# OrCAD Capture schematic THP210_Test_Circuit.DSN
size A; title: THP210 Ultra-Low Offset, High-Voltage, Low-Noise, Precision,; rev: 1.1; note: Datasheet: SBOS932C   EVM: SBOU234A
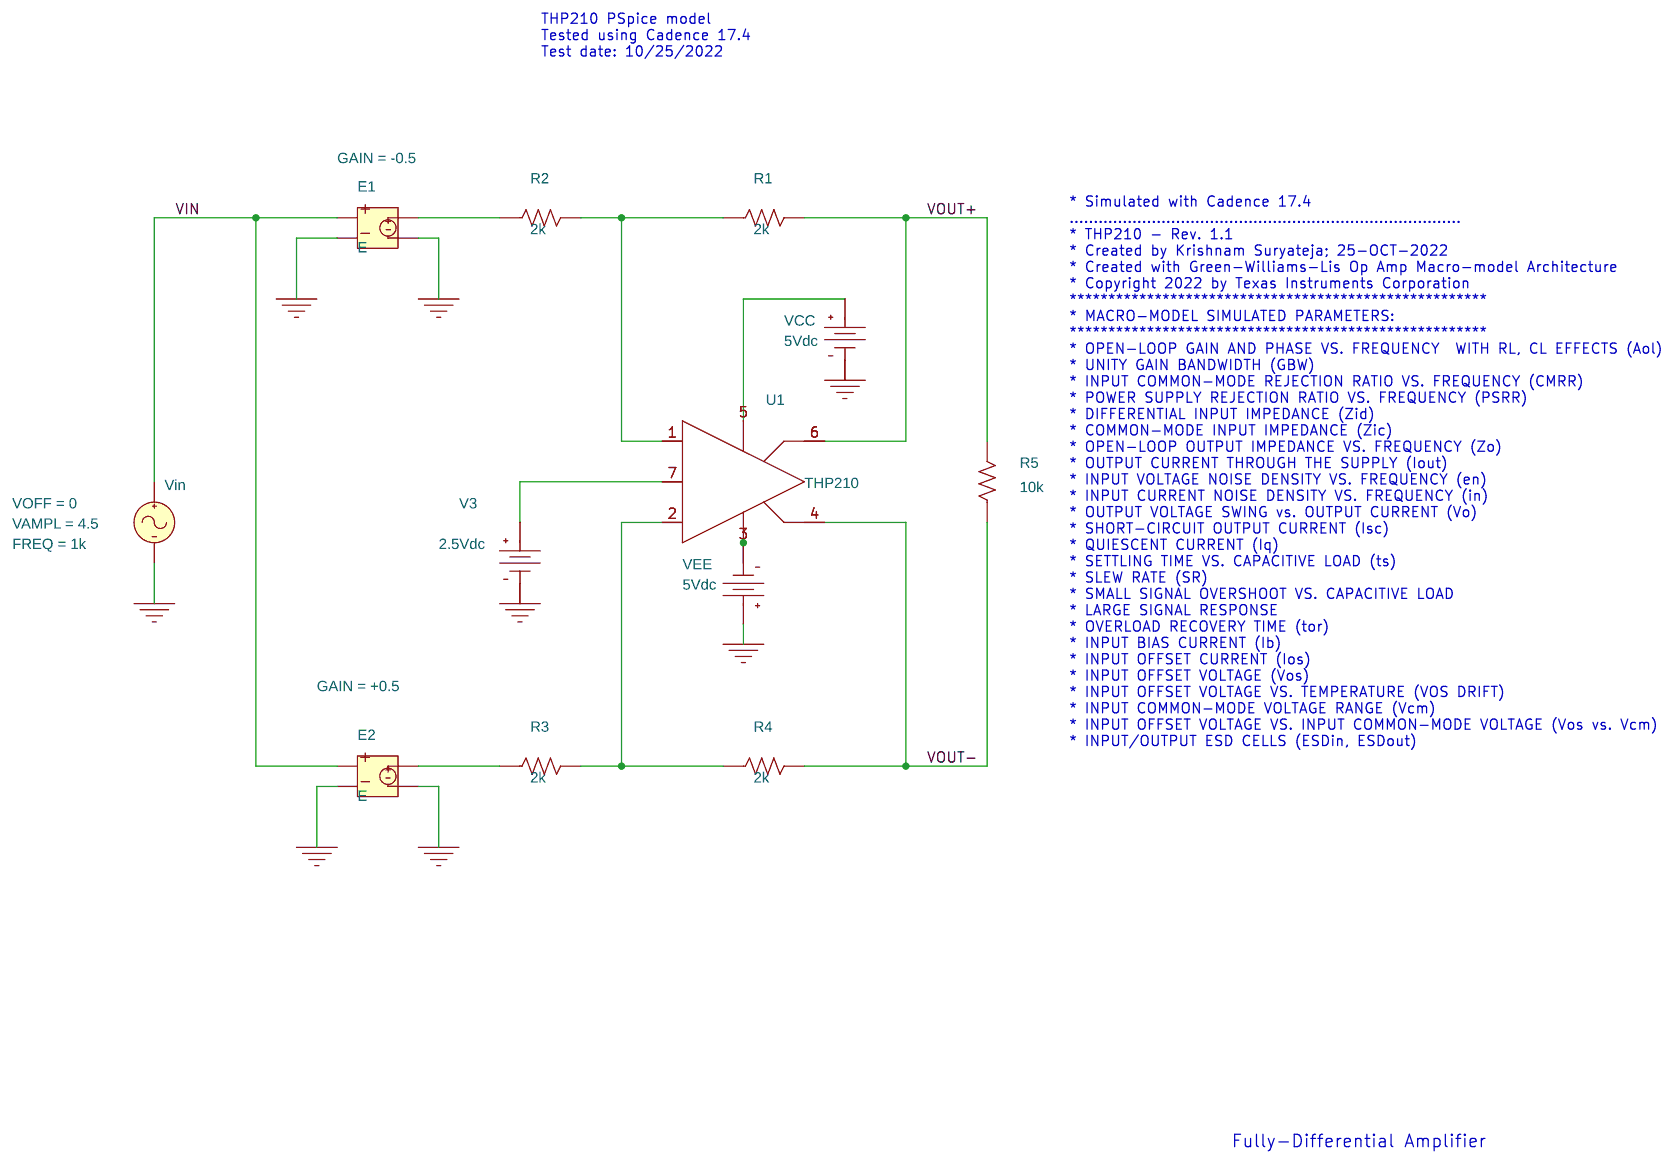
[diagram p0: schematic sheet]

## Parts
E1  E
E2  E
R1  2k  [AX/RC05]
R2  2k  [AX/RC05]
R3  2k  [AX/RC05]
R4  2k  [AX/RC05]
R5  10k  [AX/RC05]
U1  THP210
V3  VDC
VCC  VDC
VEE  VDC
Vin  VSIN

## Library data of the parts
E1 = E: GAIN: -0.5
E2 = E: GAIN: +0.5
R1-R5 = R
U1 = THP210
V3 = VDC: DC: 2.5Vdc
VCC VEE = VDC: DC: 5Vdc
Vin = VSIN: AC: 0; FREQ: 1k; VAMPL: 4.5; VOFF: 0

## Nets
VIN: E1.1 E2.1 Vin.1(+)
0: E1.2 E1.4 E2.2 E2.4 V3.1(-) VCC.1(-) VEE.0(+) Vin.2(-)
VOUT+: R1.2 R5.2 U1.6(OUT+)
VOUT-: R4.2 R5.1 U1.4(OUT-)
N00353: E2.3 R3.1
N00357: E1.3 R2.1
N00361: R1.1 R2.2 U1.1(-)
N00365: U1.5(V+) VCC.0(+)
N00386: R3.2 R4.1 U1.2(+)
N00461: U1.3(V-) VEE.1(-)
N02046: U1.7(VOCM) V3.0(+)

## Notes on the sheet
- THP210 PSpice model
  Tested using Cadence 17.4
  Test date: 10/25/2022
- * Simulated with Cadence 17.4
  .................................................................................
  * THP210 - Rev. 1.1
  * Created by Krishnam Suryateja; 25-OCT-2022
  * Created with Green-Williams-Lis Op Amp Macro-model Architecture
  * Copyright 2022 by Texas Instruments Corporation
  ******************************************************
  * MACRO-MODEL SIMULATED PARAMETERS:
  ******************************************************
  * OPEN-LOOP GAIN AND PHASE VS. FREQUENCY  WITH RL, CL EFFECTS (Aol)
  * UNITY GAIN BANDWIDTH (GBW)
  * INPUT COMMON-MODE REJECTION RATIO VS. FREQUENCY (CMRR)
  * POWER SUPPLY REJECTION RATIO VS. FREQUENCY (PSRR)
  * DIFFERENTIAL INPUT IMPEDANCE (Zid)
  * COMMON-MODE INPUT IMPEDANCE (Zic)
  * OPEN-LOOP OUTPUT IMPEDANCE VS. FREQUENCY (Zo)
  * OUTPUT CURRENT THROUGH THE SUPPLY (Iout)
  * INPUT VOLTAGE NOISE DENSITY VS. FREQUENCY (en)
  * INPUT CURRENT NOISE DENSITY VS. FREQUENCY (in)
  * OUTPUT VOLTAGE SWING vs. OUTPUT CURRENT (Vo)
  * SHORT-CIRCUIT OUTPUT CURRENT (Isc)
  * QUIESCENT CURRENT (Iq)
  * SETTLING TIME VS. CAPACITIVE LOAD (ts)
  * SLEW RATE (SR)
  * SMALL SIGNAL OVERSHOOT VS. CAPACITIVE LOAD
  * LARGE SIGNAL RESPONSE
  * OVERLOAD RECOVERY TIME (tor)
  * INPUT BIAS CURRENT (Ib)
  * INPUT OFFSET CURRENT (Ios)
  * INPUT OFFSET VOLTAGE (Vos)
  * INPUT OFFSET VOLTAGE VS. TEMPERATURE (VOS DRIFT)
  * INPUT COMMON-MODE VOLTAGE RANGE (Vcm)
  * INPUT OFFSET VOLTAGE VS. INPUT COMMON-MODE VOLTAGE (Vos vs. Vcm)
  * INPUT/OUTPUT ESD CELLS (ESDin, ESDout)
- Fully-Differential Amplifier
